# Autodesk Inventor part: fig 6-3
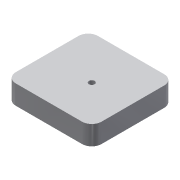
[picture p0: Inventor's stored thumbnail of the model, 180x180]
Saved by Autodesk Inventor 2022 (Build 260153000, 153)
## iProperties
Created: 2004-05
Part Number: fig 6-3
Document SubType Name: Modeling
Designer: CADCIM Technologies
Manufacturer: Standard
Standards Organization: Custom
Density: 1 g/cm^3
Material: Generic
Appearance: Default
Author: CADCIM Technologies
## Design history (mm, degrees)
sketch "Sketch1"
  geometry: L1 (0, 0)-(44.293, 0); L2 (44.293, 0)-(44.293, 42.442); L3 (44.293, 42.442)-(0, 42.442); L4 (0, 42.442)-(0, 0)
  constraints: 8 end point, 2 parallel, 1 horizontal, 1 perpendicular
extrude "Extrusion1" new body sketch "Sketch1" distance "d0" = 10; taper "d1" = 0 deg
fillet "Fillet1" dims "d2" = 5
hole "Hole1" diameter "d6" = 3; stored, may be unused: countersink angle "d10" = 90 deg, drill point angle "d12" = 118 deg; dims "d4" = 20, "d5" = 20, "d7" = 6, "d8" = 4, "d9" = 2, "d11" = 8
body "Solid1"
